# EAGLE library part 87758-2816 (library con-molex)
28 Pin - 2mm Dual Row Single Wafer, Vertical T/H HDR Source: http://www.molex.com/pdm_docs/sd/877580616_sd.pdf
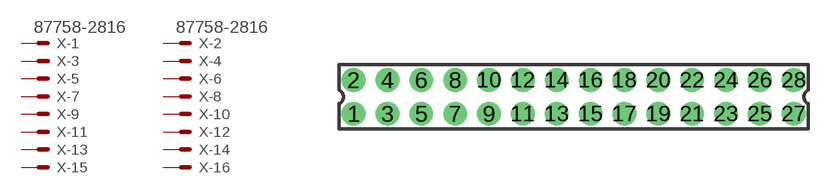
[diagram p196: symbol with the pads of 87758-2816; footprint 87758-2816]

Designator prefix X; gates -1=MV -2=MV -3=M -4=M -5=M -6=M -7=M -8=M -9=M -10=M -11=M -12=M -13=M -14=M -15=M -16=M -17=M -18=M -19=M -20=M -21=M -22=M -23=M -24=M -25=M -26=M -27=M -28=M

## 87758-2816 (MPN: 87758-2816; OC_FARNELL: unknown; OC_NEWARK: 25M5681)  [87758-2816]
1  -1:S  pas
2  -2:S  pas
3  -3:S  pas
4  -4:S  pas
5  -5:S  pas
6  -6:S  pas
7  -7:S  pas
8  -8:S  pas
9  -9:S  pas
10  -10:S  pas
11  -11:S  pas
12  -12:S  pas
13  -13:S  pas
14  -14:S  pas
15  -15:S  pas
16  -16:S  pas
17  -17:S  pas
18  -18:S  pas
19  -19:S  pas
20  -20:S  pas
21  -21:S  pas
22  -22:S  pas
23  -23:S  pas
24  -24:S  pas
25  -25:S  pas
26  -26:S  pas
27  -27:S  pas
28  -28:S  pas

## Footprint 87758-2816 (pad centres in mm)
28 Pin - 2mm Dual Row Single Wafer, Vertical T/H HDR Source: http://www.molex.com/pdm_docs/sd/877580616_sd.pdf
drill 0.9 pad 1.27 round: 1 -13,-1; 2 -13,1; 3 -11,-1; 4 -11,1; 5 -9,-1; 6 -9,1; 7 -7,-1; 8 -7,1; 9 -5,-1; 10 -5,1; 11 -3,-1; 12 -3,1; 13 -1,-1; 14 -1,1; 15 1,-1; 16 1,1; 17 3,-1; 18 3,1; 19 5,-1; 20 5,1; 21 7,-1; 22 7,1; 23 9,-1; 24 9,1; 25 11,-1; 26 11,1; 27 13,-1; 28 13,1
